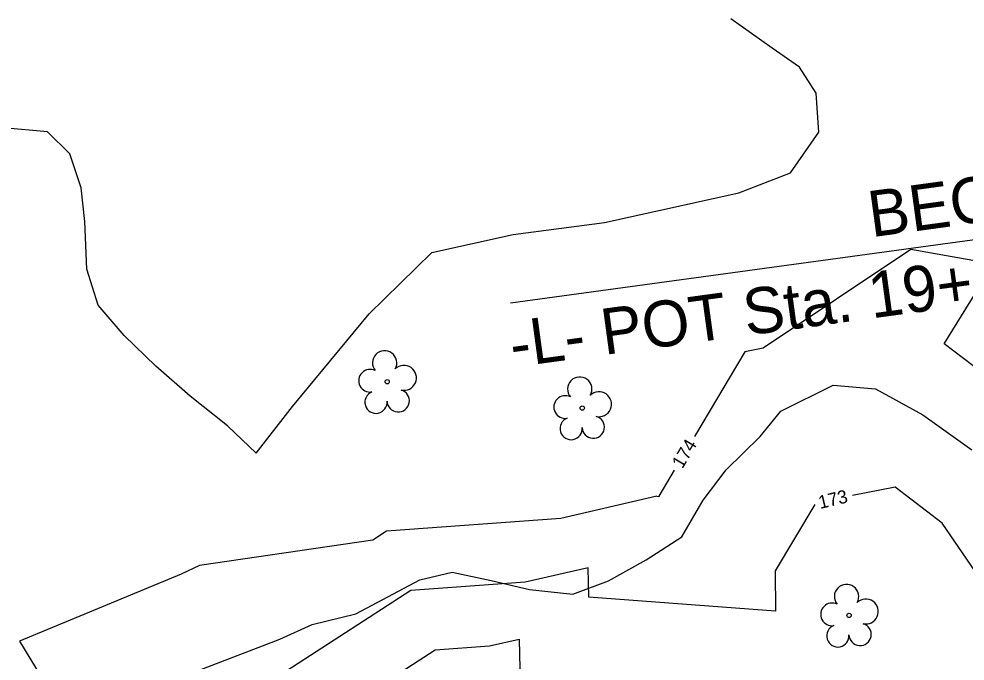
# Model space of a CAD drawing. Extents: x 2086416 to 2115205, y 575507 to 632762.
# Drawn here: x 2111776.5 to 2111920.5, y 581786.1 to 581883.8 of the extents above; entities that cross this region are included whole.
import ezdxf

# ---------------------------------------------------------------- set-up
doc = ezdxf.new("R2010")
doc.units = 0
for name, color, linetype in [('DTM Contours Minor', 7, 'Continuous'), ('DTM Contours Minor Text', 7, 'Continuous'), ('Exist Hydro Stream or Body of Water', 7, 'Continuous'), ('Exist Vegetation Tree CELL', 7, 'Continuous'), ('Prop Horizontal Alignment Station Label', 7, 'Continuous')]:
    doc.layers.add(name, color=color, linetype=linetype)

# ---------------------------------------------------------------- blocks, each defined once
blk = doc.blocks.new('EXIST VEGETATION TREE')
at = {"layer": 'Exist Vegetation Tree CELL'}
blk.add_line((0, 0), (0, 0), dxfattribs=at)
blk.add_circle((0, 0), 0.00652, dxfattribs=at)
for centre, radius, start, end in [((-0.0077, 0.0575), 0.0371, 330.1651, 219.7134), ((-0.0521, 0.0031), 0.0345, 62.6636, 279.3457), ((0.051, 0.0118), 0.038, 257.1011, 134.1999), ((0.0335, -0.058), 0.034, 181.2822, 74.56), ((-0.0341, -0.0624), 0.0338, 111.5671, 6.231)]:
    blk.add_arc(centre, radius, start, end, dxfattribs=at)

msp = doc.modelspace()

# ---------------------------------------------------------------- linework, layer by layer
at = {"layer": 'DTM Contours Minor'}
for points in [[(2111965.16, 581748.51), (2111970.69, 581749.86), (2111976.47, 581749.51), (2111981.91, 581752.5), (2111983.32, 581753.31), (2111982.36, 581755.79), (2111980.14, 581760.97), (2111975.64, 581761.52), (2111969.46, 581763.24), (2111967.22, 581769.18), (2111966.98, 581769.81), (2111965.9, 581771.13), (2111955.64, 581782.68), (2111952.51, 581790.39), (2111952, 581791.62), (2111951.36, 581791.75), (2111927.6, 581826.56), (2111917.31, 581834.4), (2111924.82, 581846.5), (2111912.24, 581848.72), (2111889.78, 581833.71), (2111886.95, 581833.16), (2111879.3, 581820.3)], [(2111876.24, 581815.15), (2111873.87, 581811.17), (2111873.87, 581811.11), (2111873.59, 581811.13), (2111873.59, 581811.18)], [(2111872.65, 581745.71), (2111876.29, 581746.03), (2111892.64, 581747.28), (2111896.68, 581747.18), (2111903.16, 581748.2), (2111906.44, 581747.76), (2111910.2, 581745.85), (2111927.92, 581748.91), (2111939.7, 581750.88), (2111951.09, 581752.85), (2111957.32, 581753.9), (2111972.19, 581756.27), (2111962.31, 581758.92), (2111961.55, 581761.08), (2111960.4, 581763.71), (2111955.81, 581769.32), (2111952.04, 581783.78), (2111951.03, 581786.21), (2111928.27, 581790.63), (2111917.03, 581807.1), (2111909.85, 581812.57), (2111903.37, 581811.31)], [(2111873.59, 581811.18), (2111858.97, 581807.81), (2111832.44, 581805.87), (2111830.33, 581804.51), (2111803.94, 581800.63), (2111801.15, 581799.34), (2111776.55, 581789.14), (2111783.31, 581778.03), (2111767.14, 581782.05), (2111752.67, 581775.15), (2111747.71, 581771.33), (2111754.42, 581760.88), (2111758.25, 581763.28), (2111765.79, 581761.52), (2111763.95, 581758.36), (2111775.89, 581748.19), (2111778.07, 581745.44)], [(2111897.63, 581809.95), (2111891.61, 581799.82), (2111891.62, 581793.7), (2111863.21, 581795.81), (2111863.1, 581800.31)], [(2111863.1, 581800.31), (2111853.52, 581798.11), (2111836.14, 581796.84), (2111810.9, 581780.53)], [(2111821.7, 581776.08), (2111839.85, 581787.81), (2111848.08, 581788.41), (2111852.61, 581789.45), (2111852.84, 581780.48), (2111902, 581776.83), (2111885.66, 581752.48), (2111856.11, 581757.42), (2111855.03, 581753.93), (2111852.8, 581746.34), (2111850.92, 581744.82), (2111848.8, 581745.28), (2111843.88, 581751.69), (2111835.91, 581751.45), (2111834.06, 581751.67), (2111828.7, 581761.88), (2111827.26, 581763.71)]]:
    msp.add_lwpolyline(points, dxfattribs=at)
at = {"layer": 'Exist Hydro Stream or Body of Water'}
for points in [[(2111812.6, 581817.73), (2111818.14, 581824.82), (2111829.78, 581838.96), (2111839.34, 581848.3), (2111851.72, 581851.02), (2111865.61, 581852.83), (2111886.05, 581857.37), (2111893.93, 581860.41), (2111898.24, 581866.59), (2111897.86, 581872.54), (2111895.28, 581876.46), (2111891.14, 581879.38), (2111884.86, 581883.82)], [(2111812.6, 581817.73), (2111808.22, 581821.88), (2111802.53, 581826.39), (2111797.29, 581830.99), (2111792.48, 581835.64), (2111788.53, 581840.26), (2111786.82, 581845.72), (2111786.48, 581853), (2111785.93, 581858.1), (2111784.22, 581863.27), (2111780.84, 581866.66), (2111774.05, 581867.27), (2111768.06, 581867.49), (2111764.65, 581868.09), (2111763.71, 581871.11), (2111762.78, 581874.58), (2111759.12, 581878.58)], [(2111816.21, 581789.41), (2111821.12, 581791.69), (2111827.75, 581793.3), (2111837.48, 581798.46), (2111842.44, 581799.62), (2111848.34, 581798.38), (2111854.2, 581797.01), (2111860.79, 581796.28), (2111866.21, 581798.32), (2111871.94, 581801.52), (2111877.38, 581805.01), (2111880.62, 581810.59), (2111884.14, 581815.18), (2111889.31, 581820.28), (2111892.48, 581824.13), (2111900.4, 581828.09), (2111906.85, 581827.54), (2111914.05, 581823.59), (2111921.52, 581818.26)], [(2111788.76, 581770.55), (2111784.43, 581763.77), (2111780.8, 581761.15), (2111778.21, 581759.21), (2111773.13, 581756.23), (2111770.68, 581759.14), (2111771.83, 581765.21), (2111776.07, 581772.13), (2111779.43, 581776.99), (2111783.88, 581782.96), (2111786.63, 581784.5), (2111789.27, 581783.19), (2111795.22, 581782.77), (2111801.4, 581783.75), (2111804.55, 581784.97), (2111816.21, 581789.41)]]:
    msp.add_lwpolyline(points, dxfattribs=at)
at = {"layer": 'Prop Horizontal Alignment Station Label'}
msp.add_line((2111851.3, 581840.64), (2111981.25, 581858.37), dxfattribs=at)

# ---------------------------------------------------------------- block references
at = {"layer": 'Exist Vegetation Tree CELL', "xscale": 50, "yscale": 50}
for p in [(2111832.53, 581828.61), (2111862.23, 581824.6), (2111902.85, 581793.05)]:
    msp.add_blockref('EXIST VEGETATION TREE', p, dxfattribs=at)

# ---------------------------------------------------------------- texts
at = {"layer": 'DTM Contours Minor Text'}
for s, rotation, p in [('174', 59.2567, (2111877.47, 581815.26)), ('173', 13.3457, (2111898.44, 581809.24))]:
    msp.add_text(s, height=2, rotation=rotation, dxfattribs=at).set_placement(p)
at = {"layer": 'Prop Horizontal Alignment Station Label'}
for s, p in [('BEGIN BRIDGE', (2111906.26, 581850.59)), (' -L- POT Sta. 19+25 +/-  ', (2111849.09, 581830.43))]:
    msp.add_text(s, height=7, rotation=7.771, dxfattribs=at).set_placement(p)

doc.saveas('drawing.dxf')
